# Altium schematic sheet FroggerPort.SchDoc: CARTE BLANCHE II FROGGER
size A2; DrawnBy: SRKH; Engineer: SRKH; DocumentNumber: 1; Revision: 2.0; SheetNumber: 1; SheetTotal: 1
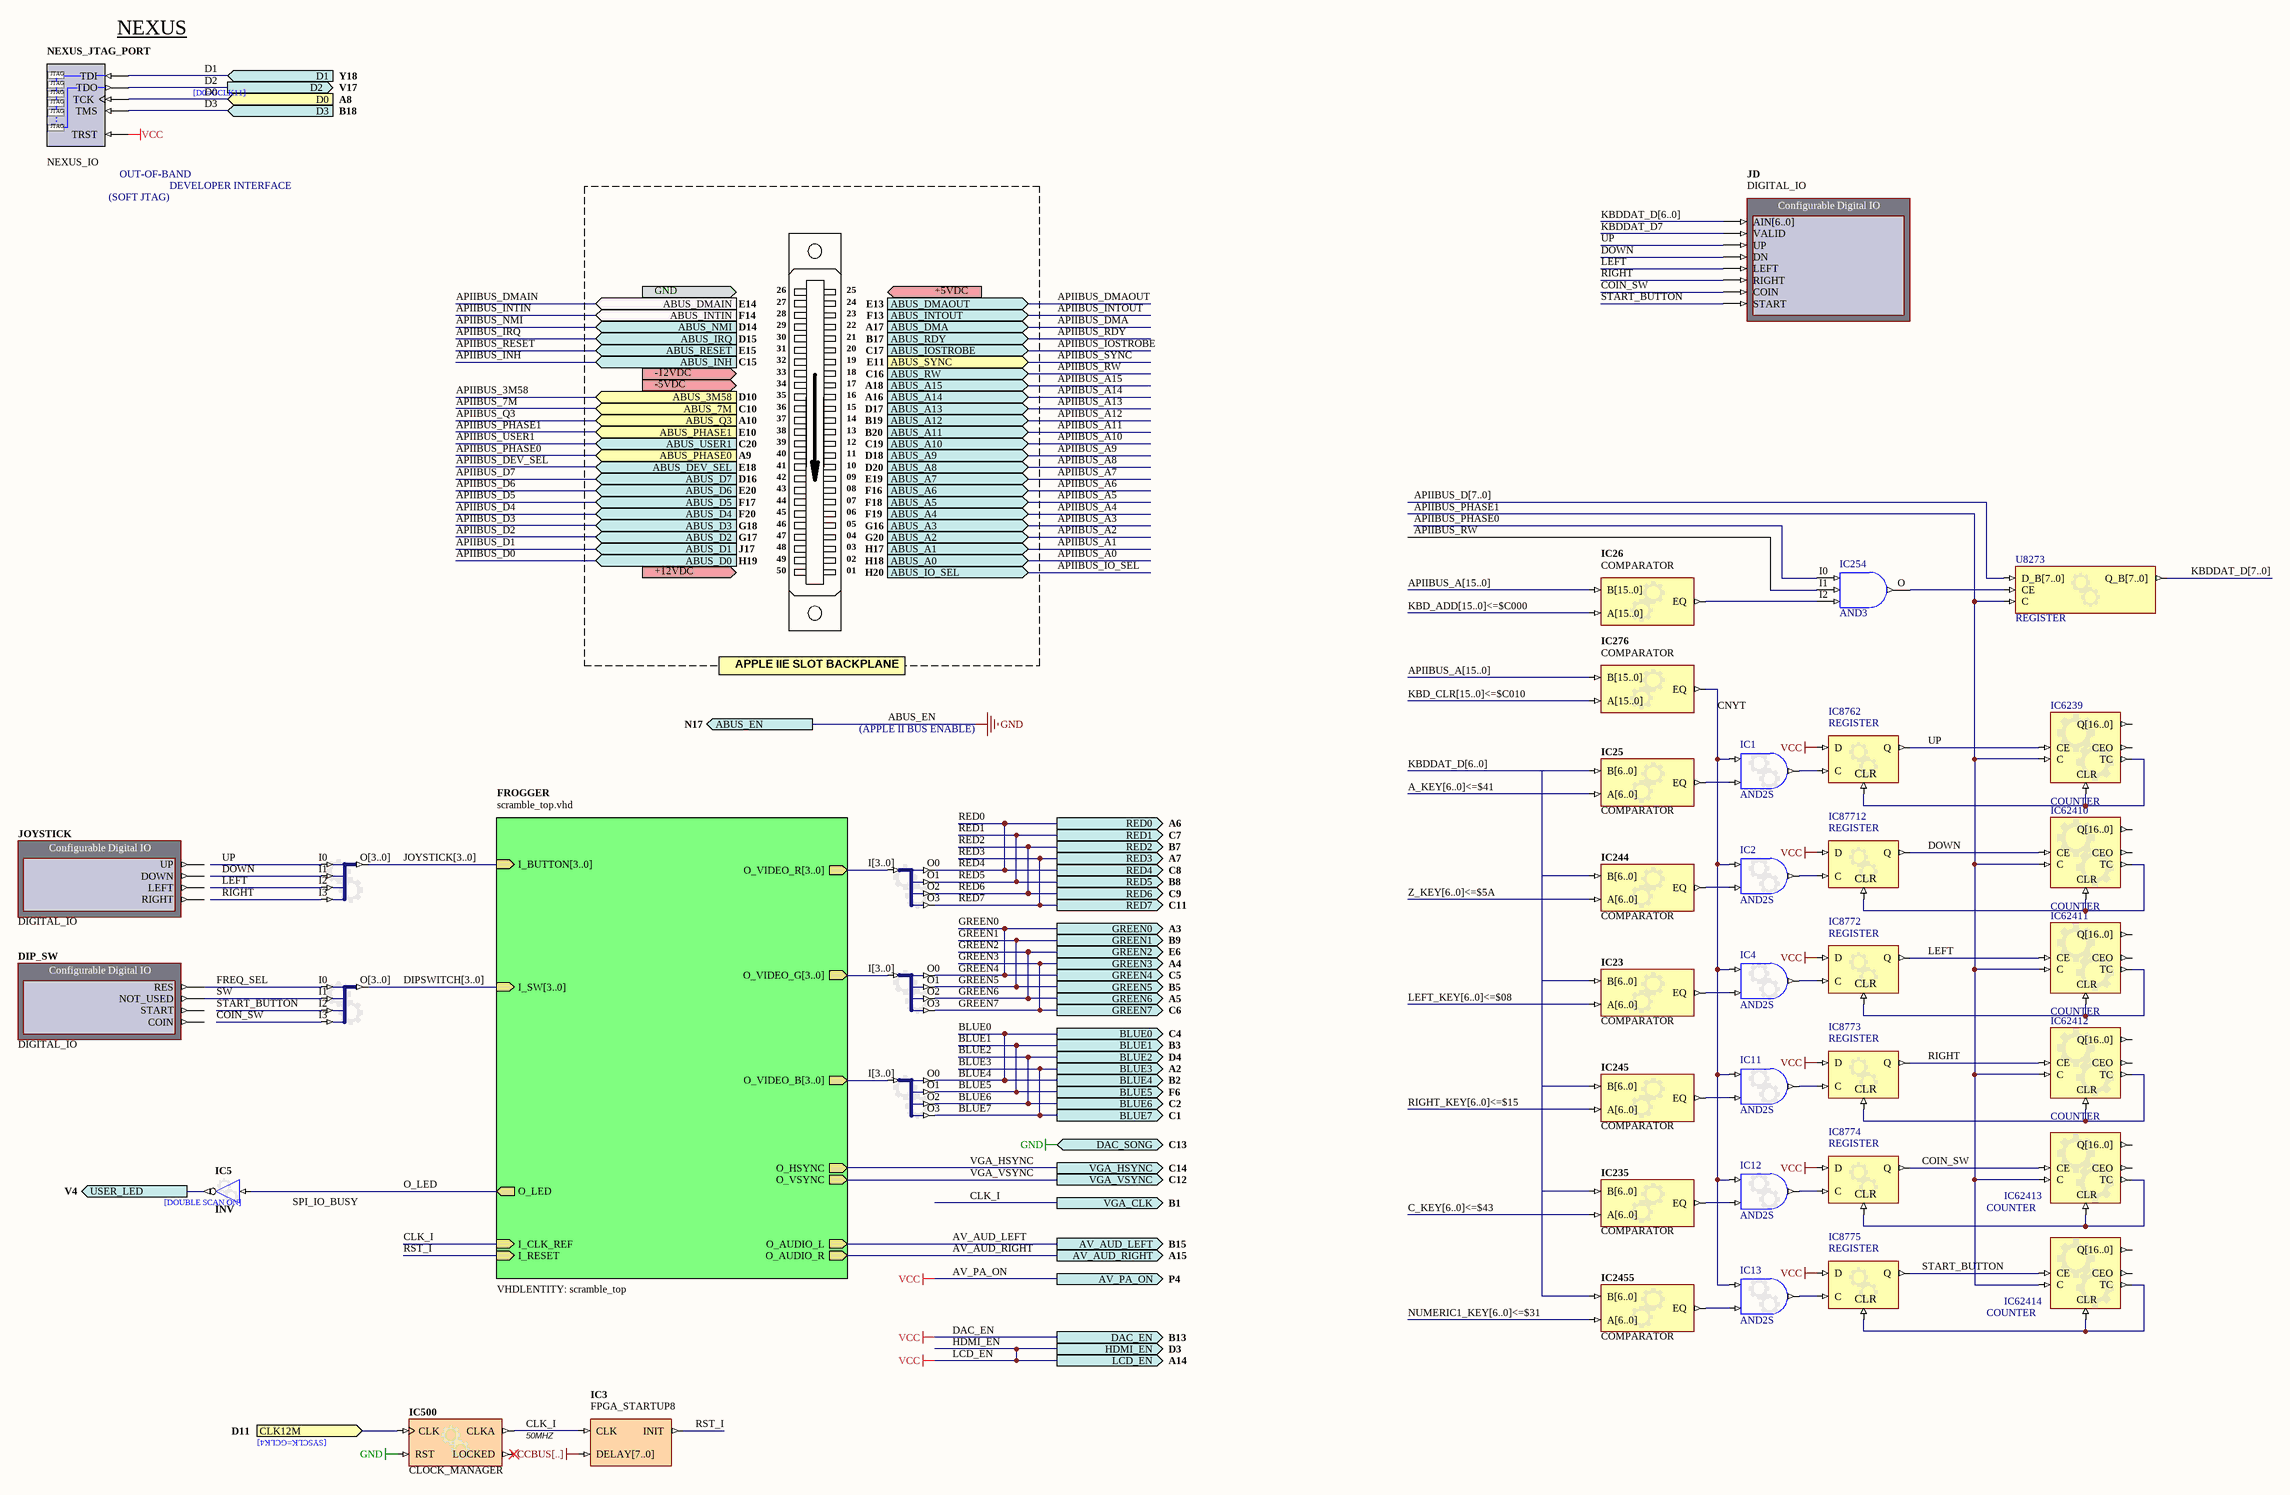
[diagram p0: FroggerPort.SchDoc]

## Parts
DIP_SW  DIGITAL_IO
IC1  AND2S
IC2  AND2S
IC3  FPGA_STARTUP8
IC4  AND2S
IC5  INV
IC6  BUS_JS  (value not drawn)
IC7  BUS_JS  (value not drawn)
IC8  BUS_JS  (value not drawn)
IC9  BUS_JS  (value not drawn)
IC10  BUS_JS  (value not drawn)
IC11  AND2S
IC12  AND2S
IC13  AND2S
IC23  COMPARATOR
IC25  COMPARATOR
IC26  COMPARATOR
IC235  COMPARATOR
IC244  COMPARATOR
IC245  COMPARATOR
IC254  AND3
IC276  COMPARATOR
IC500  CLOCK_MANAGER
IC2455  COMPARATOR
IC6239  COUNTER
IC8762  REGISTER
IC8772  REGISTER
IC8773  REGISTER
IC8774  REGISTER
IC8775  REGISTER
IC62410  COUNTER
IC62411  COUNTER
IC62412  COUNTER
IC62413  COUNTER
IC62414  COUNTER
IC87712  REGISTER
JD  DIGITAL_IO
JOYSTICK  DIGITAL_IO
NEXUS_JTAG_PORT  NEXUS_IO
U8273  REGISTER

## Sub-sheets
FROGGER = scramble_top.vhd: I_BUTTON[3..0] (in), I_CLK_REF (in), I_RESET (in), I_SW[3..0] (in), O_AUDIO_L (out), O_AUDIO_R (out), O_HSYNC (out), O_LED (out), O_VIDEO_B[3..0] (out), O_VIDEO_G[3..0] (out), O_VIDEO_R[3..0] (out), O_VSYNC (out)  | VHDLENTITY: scramble_top

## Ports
ABUS_3M58 (in, see D10), ABUS_7M (in, see C10), ABUS_A0 (in, see H18), ABUS_A1 (in, see H17), ABUS_A2 (in, see G20), ABUS_A3 (in, see G16), ABUS_A4 (in, see F19), ABUS_A5 (in, see F18), ABUS_A6 (in, see F16), ABUS_A7 (in, see E19), ABUS_A8 (in, see D20), ABUS_A9 (in, see D18), ABUS_A10 (in, see C19), ABUS_A11 (in, see B20), ABUS_A12 (in, see B19), ABUS_A13 (in, see D17), ABUS_A14 (in, see A16), ABUS_A15 (in, see A18), ABUS_D0 (in, see H19), ABUS_D1 (in, see J17), ABUS_D2 (in, see G17), ABUS_D3 (in, see G18), ABUS_D4 (in, see F20), ABUS_D5 (in, see F17), ABUS_D6 (in, see E20), ABUS_D7 (in, see D16), ABUS_DEV_SEL (in, see E18), ABUS_DMA (in, see A17), ABUS_DMAIN (in, see E14), ABUS_DMAOUT (in, see E13), ABUS_EN (out, see N17), ABUS_INH (in, see C15), ABUS_INTIN (in, see F14), ABUS_INTOUT (in, see F13), ABUS_IO_SEL (in, see H20), ABUS_IOSTROBE (in, see C17), ABUS_IRQ (in, see D15), ABUS_NMI (in, see D14), ABUS_PHASE0 (in, see A9), ABUS_PHASE1 (in, see E10), ABUS_Q3 (in, see A10), ABUS_RDY (in, see B17), ABUS_RESET (in, see E15), ABUS_RW (in, see C16), ABUS_SYNC (in, see E11), ABUS_USER1 (in, see C20), AV_AUD_LEFT (out, see B15), AV_AUD_RIGHT (out, see A15), AV_PA_ON (out, see P4), BLUE0 (out, see C4), BLUE1 (out, see B3), BLUE2 (out, see D4), BLUE3 (out, see A2), BLUE4 (out, see B2), BLUE5 (out, see F6), BLUE6 (out, see C2), BLUE7 (out, see C1), CLK12M (in, see D11), D0 (in, see A8), D1 (in, see Y18), D2 (out, see V17), D3 (in, see B18), DAC_EN (out, see B13), DAC_SONG (out, see C13), GREEN0 (out, see A3), GREEN1 (out, see B9), GREEN2 (out, see E6), GREEN3 (out, see A4), GREEN4 (out, see C5), GREEN5 (out, see B5), GREEN6 (out, see A5), GREEN7 (out, see C6), HDMI_EN (out, see D3), LCD_EN (out, see A14), RED0 (out, see A6), RED1 (out, see C7), RED2 (out, see B7), RED3 (out, see A7), RED4 (out, see C8), RED5 (out, see B8), RED6 (out, see C9), RED7 (out, see C11), USER_LED (out, see V4), VGA_CLK (out, see B1), VGA_HSYNC (out, see C14), VGA_VSYNC (out, see C12)

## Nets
ABUS_EN: IC500.RST ; port DAC_SONG, port ABUS_EN  [also labelled GND]
AV_PA_ON: IC8762.D IC8772.D IC8773.D IC8774.D IC8775.D IC87712.D NEXUS_JTAG_PORT.TRST ; port HDMI_EN, port AV_PA_ON, port DAC_EN, port LCD_EN  [also labelled DAC_EN, HDMI_EN, LCD_EN, VCC]
VCCBUS[..]: IC3.DELAY[7..0]
APIIBUS_PHASE0: IC254.I0 ; port ABUS_PHASE0
APIIBUS_PHASE1: IC6239.C IC62410.C IC62411.C IC62412.C IC62413.C IC62414.C U8273.C ; port ABUS_PHASE1
APIIBUS_RW: IC254.I1 ; port ABUS_RW
AV_AUD_LEFT: port AV_AUD_LEFT, sheet FROGGER/O_AUDIO_L
AV_AUD_RIGHT: port AV_AUD_RIGHT, sheet FROGGER/O_AUDIO_R
BLUE0: IC10.O0 ; port BLUE4, port BLUE0  [also labelled BLUE4]
BLUE1: IC10.O1 ; port BLUE5, port BLUE1  [also labelled BLUE5]
BLUE2: IC10.O2 ; port BLUE2, port BLUE6  [also labelled BLUE6]
BLUE3: IC10.O3 ; port BLUE3, port BLUE7  [also labelled BLUE7]
CLK12M: IC500.CLK ; port CLK12M
CLK_I: IC3.CLK IC500.CLKA ; port VGA_CLK, sheet FROGGER/I_CLK_REF
CNYT: IC1.I0 IC2.I0 IC4.I0 IC11.I0 IC12.I0 IC13.I0 IC276.EQ
COIN_SW: IC9.I3 IC8774.Q IC62413.CE JD.COIN
D0: NEXUS_JTAG_PORT.TCK ; port D0
D1: NEXUS_JTAG_PORT.TDI ; port D1
D2: NEXUS_JTAG_PORT.TDO ; port D2
D3: NEXUS_JTAG_PORT.TMS ; port D3
DOWN: IC6.I1 IC62410.CE IC87712.Q JD.DN
FREQ_SEL: DIP_SW.RES IC9.I0
GREEN0: IC8.O0 ; port GREEN4, port GREEN0  [also labelled GREEN4]
GREEN1: IC8.O1 ; port GREEN5, port GREEN1  [also labelled GREEN5]
GREEN2: IC8.O2 ; port GREEN2, port GREEN6  [also labelled GREEN6]
GREEN3: IC8.O3 ; port GREEN3, port GREEN7  [also labelled GREEN7]
KBDDAT_D7: JD.VALID
LEFT: IC6.I2 IC8772.Q IC62411.CE JD.LEFT
O_LED: IC5.I ; sheet FROGGER/O_LED
RED0: IC7.O0 ; port RED4, port RED0  [also labelled RED4]
RED1: IC7.O1 ; port RED5, port RED1  [also labelled RED5]
RED2: IC7.O2 ; port RED2, port RED6  [also labelled RED6]
RED3: IC7.O3 ; port RED3, port RED7  [also labelled RED7]
RIGHT: IC6.I3 IC8773.Q IC62412.CE JD.RIGHT
RST_I: IC3.INIT ; sheet FROGGER/I_RESET
START_BUTTON: IC9.I2 IC8775.Q IC62414.CE JD.START
SW: DIP_SW.NOT_USED IC9.I1
UP: IC6.I0 IC6239.CE IC8762.Q JD.UP
USER_LED: IC5.O ; port USER_LED
VGA_HSYNC: port VGA_HSYNC, sheet FROGGER/O_HSYNC
VGA_VSYNC: port VGA_VSYNC, sheet FROGGER/O_VSYNC
NetIC1_I1: IC1.I1 IC25.EQ
NetIC1_O: IC1.O IC8762.C
NetIC2_I1: IC2.I1 IC244.EQ
NetIC2_O: IC2.O IC87712.C
NetIC4_I1: IC4.I1 IC23.EQ
NetIC4_O: IC4.O IC8772.C
NetIC11_I1: IC11.I1 IC245.EQ
NetIC11_O: IC11.O IC8773.C
NetIC12_I1: IC12.I1 IC235.EQ
NetIC12_O: IC12.O IC8774.C
NetIC13_I1: IC13.I1 IC2455.EQ
NetIC13_O: IC13.O IC8775.C
NetIC26_EQ: IC26.EQ IC254.I2
NetIC254_O: IC254.O U8273.CE
NetIC6239_CLR: IC6239.CLR IC6239.TC IC8762.CLR
NetIC8772_CLR: IC8772.CLR IC62411.CLR IC62411.TC
NetIC8773_CLR: IC8773.CLR IC62412.CLR IC62412.TC
NetIC8774_CLR: IC8774.CLR IC62413.CLR IC62413.TC
NetIC8775_CLR: IC8775.CLR IC62414.CLR IC62414.TC
NetIC62410_CLR: IC62410.CLR IC62410.TC IC87712.CLR

Not connected (* = marked no-connect by the designer): DIP_SW COIN START; IC6 O[3..0]; IC7 I[3..0]; IC8 I[3..0]; IC9 O[3..0]; IC10 I[3..0]; IC23 A[6..0] B[6..0]; IC25 A[6..0] B[6..0]; IC26 A[15..0] B[15..0]; IC235 A[6..0] B[6..0]; IC244 A[6..0] B[6..0]; IC245 A[6..0] B[6..0]; IC276 A[15..0] B[15..0]; IC500 LOCKED*; IC2455 A[6..0] B[6..0]; IC6239 CEO Q[16..0]; IC62410 CEO Q[16..0]; IC62411 CEO Q[16..0]; IC62412 CEO Q[16..0]; IC62413 CEO Q[16..0]; IC62414 CEO Q[16..0]; JD AIN[6..0]; JOYSTICK DOWN LEFT RIGHT UP; U8273 D_B[7..0] Q_B[7..0]

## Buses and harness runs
bus A_KEY[6..0]<=$41
bus APIIBUS_A[15..0]
bus APIIBUS_D[7..0]
bus C_KEY[6..0]<=$43
bus DIPSWITCH[3..0] = sheet FROGGER/I_SW[3..0]
bus JOYSTICK[3..0] = sheet FROGGER/I_BUTTON[3..0]
bus KBD_ADD[15..0]<=$C000
bus KBD_CLR[15..0]<=$C010
bus KBDDAT_D[6..0]
bus KBDDAT_D[7..0]
bus LEFT_KEY[6..0]<=$08
bus NUMERIC1_KEY[6..0]<=$31
bus RIGHT_KEY[6..0]<=$15
bus Z_KEY[6..0]<=$5A

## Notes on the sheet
- (near NEXUS_JTAG_PORT) NEXUS
- (near NEXUS_JTAG_PORT) [D0=GCLK11]
- (near NEXUS_JTAG_PORT) OUT-OF-BAND
- (SOFT JTAG)
- DEVELOPER INTERFACE
- GND
- 26
- 25
- +5VDC
- 27
- 28
- 29
- 30
- 31
- 24
- 23
- 22
- 21
- 20
- -12VDC
- -5VDC
- 32
- 33
- 34
- 35
- 36
- 19
- 18
- 17
- 16
- 15
- 37
- 38
- 39
- 40
- 41
- 14
- 13
- 12
- 11
- 10
- 42
- 43
- 44
- 45
- 46
- 09
- 08
- 07
- 06
- 05
- +12VDC
- 47
- 48
- 49
- 50
- 04
- 03
- 02
- 01
- APPLE IIE SLOT BACKPLANE
- (APPLE II BUS ENABLE)
- [DOUBLE SCAN ON]
- [SYSCLK=GCLK4]
- (near IC500) 50MHZ
- Labels drawn without touching a wire or pin: SPI_IO_BUSY

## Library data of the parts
DIP_SW = DIGITAL_IO: Configurable Digital IO; NEXUS_CORE: Instrument; NEXUS_JTAG_DEVICE: True; NEXUS_JTAG_ORDER: 0; ConfigurationParameters: {}Version[2.0]{}StorageType[3]{}InterfaceType[Parallel]{}SchCompWidth[140]{}NoInputs[ ]{}Output0Name[RES]{}Output0Width[1]{}Output0InitValue[15]{}Output0Kind[LEDs]{}Output0LEDStyle[Red]{}Output1Name[NOT_USED]{}Output1Width[1]{}Output1InitValue[0]{}Output1Kind[LEDs]{}Output1LEDStyle[Red]{}Output2Name[START]{}Output2Width[1]{}Output2InitValue[15]{}Output2Kind[LEDs]{}Output2LEDStyle[Red]{}Output3Name[COIN]{}Output3Width[1]{}Output3InitValue[15]{}Output3Kind[LEDs]{}Output3LEDStyle[Red]{}Designator[DIP_SW]{}InternalID[1]{}
IC1 IC2 IC4 IC11-IC13 = GATE: Configurable Generic Gate; ConfiguratorName: GENERIC_GATE; ConfigurationParameters: {}Version[1.1]{}GateKind[AND]{}BusInput[False]{}GateInputType[Bit]{}GateOutputOption[Normal]{}BusWidth[8]{}RegisterOutputs[False]{}NegativeClockEdge[False]{}InputCount[2]{}InputInvert0[False]{}InputInvert1[False]{}
IC3 = FPGA_STARTUP8: FPGA Startup With 8 Bit Delay
IC5 = INV: Configurable Inverter; ConfiguratorName: GENERIC_BUFFER; ConfigurationParameters: {}Version[1.1]{}SignalCount[1]{}SignalWidth0[1]{}OutputOption0[Inverted]{}EnableMode[None]{}ShowPinNames[False]{}
IC6 IC9 = BUS_JS: Configurable Bus Joiner/Splitter; ConfiguratorName: GENERIC_BUS_JS; ConfigurationParameters: {}Version[1.1]{}SplitterJoinerType[Joiner]{}SignalCount[4]{}SignalWidth0[1]{}GapBelow0[1000000]{}ConnectionType0[Pin]{}SignalWidth1[1]{}GapBelow1[1000000]{}ConnectionType1[Pin]{}SignalWidth2[1]{}GapBelow2[1000000]{}ConnectionType2[Pin]{}SignalWidth3[1]{}GapBelow3[1000000]{}ConnectionType3[Pin]{}ShowPinNames[True]{}
IC7 IC8 IC10 = BUS_JS: Configurable Bus Joiner/Splitter; ConfiguratorName: GENERIC_BUS_JS; ConfigurationParameters: {}Version[1.1]{}SplitterJoinerType[Splitter]{}SignalCount[4]{}SignalWidth0[1]{}GapBelow0[1000000]{}ConnectionType0[Pin]{}SignalWidth1[1]{}GapBelow1[1000000]{}ConnectionType1[Pin]{}SignalWidth2[1]{}GapBelow2[1000000]{}ConnectionType2[Pin]{}SignalWidth3[1]{}GapBelow3[1000000]{}ConnectionType3[Pin]{}ShowPinNames[True]{}
IC23 IC25 IC235 IC244 IC245 IC2455 = COMPARATOR: Configurable Comparator; ConfiguratorName: GENERIC_COMPARATOR; ConfigurationParameters: {}Version[1.0]{}EQ[True]{}GT[False]{}LT[False]{}SignalWidth[7]{}BusInputs[True]{}RegisterOutputs[False]{}NegClockEdge[False]{}
IC26 IC276 = COMPARATOR: Configurable Comparator; ConfiguratorName: GENERIC_COMPARATOR; ConfigurationParameters: {}Version[1.0]{}EQ[True]{}GT[False]{}LT[False]{}SignalWidth[16]{}BusInputs[True]{}RegisterOutputs[False]{}NegClockEdge[False]{}
IC254 = AND3: 3-Input AND Gate; FPGAVendor: Xilinx
IC500 = CLOCKMANAGER: Configurable Clock Manager; ConfiguratorName: GENERIC_CLOCKMANAGER; ConfigurationParameters: {}Version[1.0]{}Option_Configuration[object _1: TClockManagerPersist / VersionMajor [ 0 / VersionMinor [ 0 / InputFreq [ 24.000000000000000000 / InputName [ 'CLK' / OutputTargets [ < / item / Name [ 'CLKA' / OutFreqMin [ 98.010000000000010000 / OutFreqMax [ 99.989999999999990000 / OutPostDivider [ 1.000000000000000000 / end> / OutputDevices [ < / item / Name [ 'Spartan3AN' / Valid [ True / OutputActuals [ < / item / Name [ 'CLK0' / Multipler [ 1.000000000000000000 / Divider [ 1.000000000000000000 / OutFreq [ 24.000000000000000000 / OutputMap [ 1 / end / item / Name [ 'CLK90' / Multipler [ 1.000000000000000000 / Divider [ 1.000000000000000000 / OutPhase [ 90.000000000000000000 / OutFreq [ 24.000000000000000000 / OutputMap [ 2 / end / item / Name [ 'CLK180' / Multipler [ 1.000000000000000000 / Divider [ 1.000000000000000000 / OutPhase [ 180.000000000000000000 / OutFreq [ 24.000000000000000000 / OutputMap [ 3 / end / item / Name [ 'CLK270' / Multipler [ 1.000000000000000000 / Divider [ 1.000000000000000000 / OutPhase [ 270.000000000000000000 / OutFreq [ 24.000000000000000000 / OutputMap [ 4 / end / item / Name [ 'CLK2X' / Multipler [ 2.000000000000000000 / Divider [ 1.000000000000000000 / OutFreq [ 48.000000000000000000 / OutputMap [ 5 / end / item / Name [ 'CLKDV' / Multipler [ 1.000000000000000000 / Divider [ 16.000000000000000000 / OutFreq [ 1.500000000000000000 / OutputMap [ 6 / end / item / Name [ 'CLK2X180' / Multipler [ 1.000000000000000000 / Divider [ 1.000000000000000000 / OutPhase [ 180.000000000000000000 / OutFreq [ 48.000000000000000000 / OutputMap [ 7 / end / item / Name [ 'CLKFX' / Multipler [ 29.000000000000000000 / Divider [ 7.000000000000000000 / OutFreq [ 99.428571428571430000 / OutputMap [ 0 / end / item / Name [ 'CLKFX180' / Multipler [ 1.000000000000000000 / Divider [ 1.000000000000000000 / OutPhase [ 180.000000000000000000 / OutFreq [ 99.428571428571430000 / OutputMap [ 8 / end> / InternalActuals [ <> / CustomVars [ <> / end> / MinInputFreq [ 1.000000000000000000 / MaxInputFreq [ 280.000000000000000000 / MinOutputFreq [ 18.000000000000000000 / MaxOutputFreq [ 210.000000000000000000 / MaxOutputCount [ 9 / end]{}
IC6239 IC62410-IC62414 = COUNTER: Configurable Counter; ConfiguratorName: GENERIC_COUNTER; ConfigurationParameters: {}Version[1.0]{}Type[Binary]{}SyncReset[False]{}NegativeClockEdge[False]{}FixedDirection[True]{}IsIncrement[True]{}SignalWidth[17]{}MaxValue[100000]{}BusOutput[True]{}Loadable[False]{}BusInput[False]{}
IC8762 IC8772-IC8775 IC87712 = REGISTER: Configurable Register; ConfiguratorName: GENERIC_REGISTER; ConfigurationParameters: {}Version[1.1]{}RegisterType[DFlipFlop]{}NegativeTrigger[False]{}TriggerEnable[False]{}ResetMode[Asynchronous]{}SetMode[None]{}SignalCount[1]{}SignalWidth0[1]{}OutputOption0[Normal]{}
JD = DIGITAL_IO: Configurable Digital IO; NEXUS_CORE: Instrument; NEXUS_JTAG_DEVICE: True; NEXUS_JTAG_ORDER: 0; ConfigurationParameters: {}Version[2.0]{}StorageType[3]{}InterfaceType[Parallel]{}SchCompWidth[140]{}Input0Name[AIN{1}6..0{2}]{}Input0Width[7]{}Input0InitValue[0]{}Input0Kind[Numeric]{}Input0NumRadix[Decimal]{}Input1Name[VALID]{}Input1Width[1]{}Input1InitValue[0]{}Input1Kind[LEDs]{}Input1LEDStyle[Green]{}Input2Name[UP]{}Input2Width[1]{}Input2InitValue[0]{}Input2Kind[LEDs]{}Input2LEDStyle[Red]{}Input3Name[DN]{}Input3Width[1]{}Input3InitValue[0]{}Input3Kind[LEDs]{}Input3LEDStyle[Red]{}Input4Name[LEFT]{}Input4Width[1]{}Input4InitValue[0]{}Input4Kind[LEDs]{}Input4LEDStyle[Red]{}Input5Name[RIGHT]{}Input5Width[1]{}Input5InitValue[0]{}Input5Kind[LEDs]{}Input5LEDStyle[Red]{}Input6Name[COIN]{}Input6Width[1]{}Input6InitValue[0]{}Input6Kind[LEDs]{}Input6LEDStyle[Red]{}Input7Name[START]{}Input7Width[1]{}Input7InitValue[0]{}Input7Kind[LEDs]{}Input7LEDStyle[Red]{}NoOutputs[ ]{}Designator[JD]{}InternalID[2]{}
JOYSTICK = DIGITAL_IO: Configurable Digital IO; NEXUS_CORE: Instrument; NEXUS_JTAG_DEVICE: True; NEXUS_JTAG_ORDER: 0; ConfigurationParameters: {}Version[2.0]{}StorageType[3]{}InterfaceType[Parallel]{}SchCompWidth[140]{}NoInputs[ ]{}Output0Name[UP]{}Output0Width[1]{}Output0InitValue[0]{}Output0Kind[LEDs]{}Output0LEDStyle[Green]{}Output1Name[DOWN]{}Output1Width[1]{}Output1InitValue[0]{}Output1Kind[LEDs]{}Output1LEDStyle[Green]{}Output2Name[LEFT]{}Output2Width[1]{}Output2InitValue[0]{}Output2Kind[LEDs]{}Output2LEDStyle[Green]{}Output3Name[RIGHT]{}Output3Width[1]{}Output3InitValue[0]{}Output3Kind[LEDs]{}Output3LEDStyle[Green]{}Designator[JOYSTICK]{}InternalID[3]{}
NEXUS_JTAG_PORT = NEXUS_JTAG_PORT: Soft Nexus-Chain Connector; NEXUS_JTAG_CONNECTOR: True
U8273 = REGISTER: Configurable Register; ConfiguratorName: GENERIC_REGISTER; ConfigurationParameters: {}Version[1.1]{}RegisterType[DFlipFlop]{}NegativeTrigger[False]{}TriggerEnable[True]{}ResetMode[None]{}SetMode[None]{}SignalCount[1]{}SignalWidth0[8]{}OutputOption0[Normal]{}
